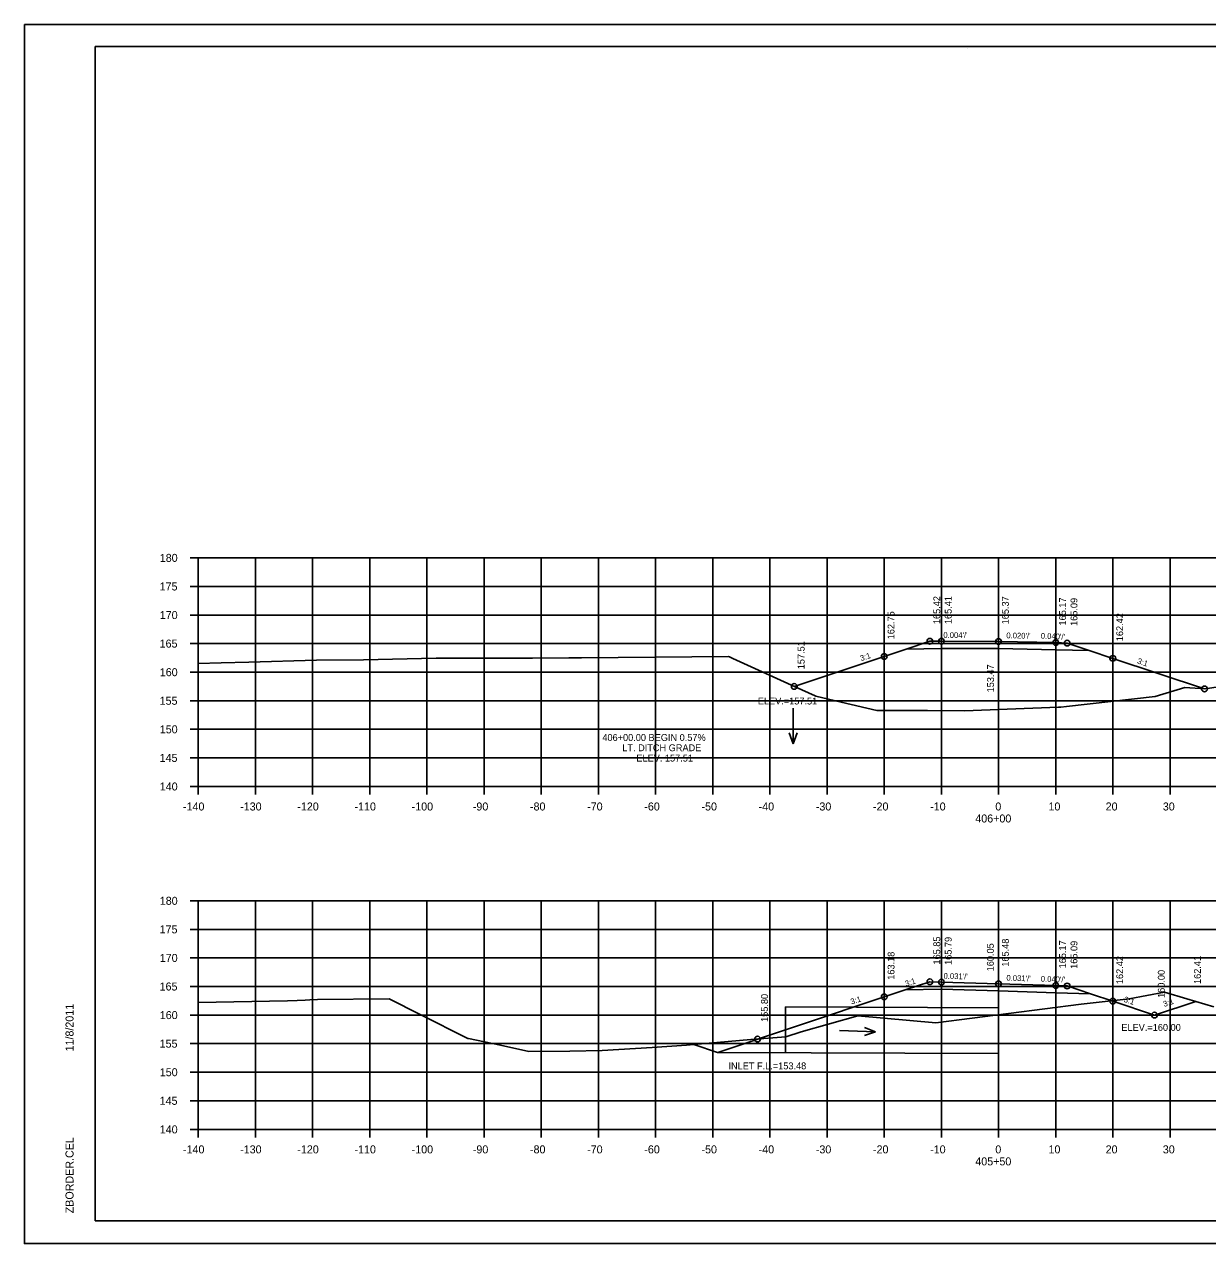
# Model space of a CAD drawing. Extents: x 1368503 to 1373085, y 379840 to 381833.
# Drawn here: x 1372751.7 to 1372958.7, y 380601.6 to 380815 of the extents above; entities that cross this region are included whole.
import ezdxf

# ---------------------------------------------------------------- set-up
doc = ezdxf.new("R2010")
doc.units = 0
for name, color, linetype in [('S_BREAKLINE', 7, 'Continuous'), ('S_BRIDGE', 7, 'Continuous'), ('S_EDGE_PAVEMENT', 7, 'Continuous'), ('S_GRAVEL_ROAD', 7, 'Continuous'), ('S_MISC_BOUNDARY', 7, 'Continuous'), ('S_OBSCURES', 7, 'Continuous'), ('S_PHOTO_CENTERS', 7, 'Continuous'), ('S_PHOTO_NOTES', 7, 'Continuous'), ('S_RDW_PT_SYM', 7, 'Continuous'), ('S_SHOULDER', 7, 'Continuous'), ('S_STREAM_ANNOT', 7, 'Continuous'), ('S_TRAILS', 7, 'Continuous'), ('S_TRAILS_ANNOT', 7, 'Continuous')]:
    doc.layers.add(name, color=color, linetype=linetype)

msp = doc.modelspace()

# ---------------------------------------------------------------- linework, layer by layer
at = {"layer": 'S_BREAKLINE'}
for p, q in [((1372884.84, 380643.05), (1372922.08, 380642.91)), ((1372884.84, 380635.05), (1372884.84, 380643.05)), ((1372872.94, 380635.09), (1372868.79, 380636.48)), ((1372872.94, 380635.09), (1372922.08, 380634.91))]:
    msp.add_line(p, q, dxfattribs=at)
at = {"layer": 'S_BRIDGE'}
for p, q in [((1372764.08, 380811.09), (1373080.26, 380811.09)), ((1372764.08, 380605.63), (1372764.08, 380811.09)), ((1372916.6, 380810.83), (1372916.6, 380810.83)), ((1372916.6, 380810.83), (1372916.6, 380810.83)), ((1372764.08, 380605.63), (1372764.08, 380605.63)), ((1373080.26, 380605.63), (1372764.08, 380605.63))]:
    msp.add_line(p, q, dxfattribs=at)
at = {"layer": 'S_EDGE_PAVEMENT'}
for p, q in [((1372780.68, 380721.63), (1372782.08, 380721.63)), ((1372782.08, 380681.63), (1372782.08, 380721.63)), ((1372780.68, 380716.63), (1372782.08, 380716.63)), ((1372780.68, 380711.63), (1372782.08, 380711.63)), ((1372780.68, 380706.63), (1372782.08, 380706.63)), ((1372780.68, 380701.63), (1372782.08, 380701.63)), ((1372780.68, 380696.63), (1372782.08, 380696.63)), ((1372780.68, 380691.63), (1372782.08, 380691.63)), ((1372780.68, 380686.63), (1372782.08, 380686.63)), ((1372780.68, 380681.63), (1372782.08, 380681.63)), ((1372782.08, 380681.63), (1373062.08, 380681.63)), ((1372782.08, 380680.23), (1372782.08, 380681.63)), ((1372792.08, 380680.23), (1372792.08, 380681.63)), ((1372802.08, 380680.23), (1372802.08, 380681.63)), ((1372812.08, 380680.23), (1372812.08, 380681.63)), ((1372822.08, 380680.23), (1372822.08, 380681.63)), ((1372832.08, 380680.23), (1372832.08, 380681.63)), ((1372842.08, 380680.23), (1372842.08, 380681.63)), ((1372852.08, 380680.23), (1372852.08, 380681.63)), ((1372862.08, 380680.23), (1372862.08, 380681.63)), ((1372872.08, 380680.23), (1372872.08, 380681.63)), ((1372882.08, 380680.23), (1372882.08, 380681.63)), ((1372892.08, 380680.23), (1372892.08, 380681.63)), ((1372902.08, 380680.23), (1372902.08, 380681.63)), ((1372912.08, 380680.23), (1372912.08, 380681.63)), ((1372922.08, 380680.23), (1372922.08, 380681.63)), ((1372932.08, 380680.23), (1372932.08, 380681.63)), ((1372942.08, 380680.23), (1372942.08, 380681.63)), ((1372952.08, 380680.23), (1372952.08, 380681.63)), ((1372780.68, 380661.63), (1372782.08, 380661.63)), ((1372782.08, 380621.63), (1372782.08, 380661.63)), ((1372780.68, 380656.63), (1372782.08, 380656.63)), ((1372780.68, 380651.63), (1372782.08, 380651.63)), ((1372780.68, 380646.63), (1372782.08, 380646.63)), ((1372780.68, 380641.63), (1372782.08, 380641.63)), ((1372780.68, 380636.63), (1372782.08, 380636.63)), ((1372780.68, 380631.63), (1372782.08, 380631.63)), ((1372780.68, 380626.63), (1372782.08, 380626.63)), ((1372780.68, 380621.63), (1372782.08, 380621.63)), ((1372782.08, 380621.63), (1373062.08, 380621.63)), ((1372782.08, 380620.23), (1372782.08, 380621.63)), ((1372792.08, 380620.23), (1372792.08, 380621.63)), ((1372802.08, 380620.23), (1372802.08, 380621.63)), ((1372812.08, 380620.23), (1372812.08, 380621.63)), ((1372822.08, 380620.23), (1372822.08, 380621.63)), ((1372832.08, 380620.23), (1372832.08, 380621.63)), ((1372842.08, 380620.23), (1372842.08, 380621.63)), ((1372852.08, 380620.23), (1372852.08, 380621.63)), ((1372862.08, 380620.23), (1372862.08, 380621.63)), ((1372872.08, 380620.23), (1372872.08, 380621.63)), ((1372882.08, 380620.23), (1372882.08, 380621.63)), ((1372892.08, 380620.23), (1372892.08, 380621.63)), ((1372902.08, 380620.23), (1372902.08, 380621.63)), ((1372912.08, 380620.23), (1372912.08, 380621.63)), ((1372922.08, 380620.23), (1372922.08, 380621.63)), ((1372932.08, 380620.23), (1372932.08, 380621.63)), ((1372942.08, 380620.23), (1372942.08, 380621.63)), ((1372952.08, 380620.23), (1372952.08, 380621.63))]:
    msp.add_line(p, q, dxfattribs=at)
at = {"layer": 'S_GRAVEL_ROAD'}
for p, q in [((1372886.17, 380695.36), (1372886.17, 380689.08)), ((1372886.17, 380689.08), (1372885.47, 380691)), ((1372886.17, 380689.08), (1372886.87, 380691)), ((1372900.55, 380638.7), (1372898.65, 380639.46)), ((1372894.27, 380638.91), (1372900.55, 380638.7)), ((1372900.55, 380638.7), (1372898.61, 380638.06))]:
    msp.add_line(p, q, dxfattribs=at)
at = {"layer": 'S_MISC_BOUNDARY'}
for points in [[(1372782.08, 380703.12), (1372786.08, 380703.24), (1372790.94, 380703.39), (1372802.76, 380703.74), (1372811, 380703.78), (1372823.72, 380704.09), (1372840.53, 380704.09), (1372846.89, 380704.12), (1372849.14, 380704.13), (1372874.87, 380704.37), (1372875.04, 380704.29), (1372875.62, 380704.03), (1372886.51, 380699.07), (1372890.03, 380697.47), (1372890.11, 380697.46), (1372890.12, 380697.45), (1372894.57, 380696.41), (1372900.78, 380694.94), (1372909.63, 380694.94), (1372916.11, 380694.86), (1372932.59, 380695.49), (1372932.98, 380695.51), (1372933.98, 380695.62), (1372949.5, 380697.4), (1372949.5, 380697.4), (1372949.51, 380697.4), (1372954.65, 380698.96), (1372958.21, 380698.7), (1372960.17, 380698.99)], [(1372782.08, 380643.85), (1372797.72, 380644.15), (1372799.4, 380644.21), (1372800.79, 380644.26), (1372801.6, 380644.29), (1372802.97, 380644.34), (1372815.49, 380644.49), (1372820.89, 380641.73), (1372829.26, 380637.53), (1372829.28, 380637.53), (1372829.39, 380637.52), (1372834.97, 380636.36), (1372839.91, 380635.27), (1372847.08, 380635.29), (1372852.76, 380635.41), (1372861.51, 380635.98), (1372867.52, 380636.37), (1372878.75, 380637.33), (1372884.87, 380637.81), (1372884.88, 380637.81), (1372884.89, 380637.82), (1372887.58, 380638.68), (1372897.49, 380641.47), (1372911.09, 380640.27), (1372936.53, 380643.54), (1372944.92, 380644.46), (1372951.14, 380645.64), (1372955.01, 380644.49), (1372959.73, 380643.1)]]:
    msp.add_lwpolyline(points, dxfattribs=at)
at = {"layer": 'S_OBSCURES'}
for points in [[(1372937.94, 380705.43), (1372932.08, 380705.55), (1372922.08, 380705.75), (1372912.08, 380705.79), (1372905.94, 380705.66)], [(1372938.15, 380645.36), (1372932.08, 380645.55), (1372922.08, 380645.85), (1372912.08, 380646.16), (1372905.77, 380646.04)]]:
    msp.add_lwpolyline(points, dxfattribs=at)
at = {"layer": 'S_PHOTO_CENTERS'}
for p, q in [((1372782.08, 380721.63), (1373062.08, 380721.63)), ((1372782.08, 380681.63), (1372782.08, 380721.63)), ((1372792.08, 380681.63), (1372792.08, 380721.63)), ((1372802.08, 380681.63), (1372802.08, 380721.63)), ((1372812.08, 380681.63), (1372812.08, 380721.63)), ((1372822.08, 380681.63), (1372822.08, 380721.63)), ((1372832.08, 380681.63), (1372832.08, 380721.63)), ((1372842.08, 380681.63), (1372842.08, 380721.63)), ((1372852.08, 380681.63), (1372852.08, 380721.63)), ((1372862.08, 380681.63), (1372862.08, 380721.63)), ((1372872.08, 380681.63), (1372872.08, 380721.63)), ((1372882.08, 380681.63), (1372882.08, 380721.63)), ((1372892.08, 380681.63), (1372892.08, 380721.63)), ((1372902.08, 380681.63), (1372902.08, 380721.63)), ((1372912.08, 380681.63), (1372912.08, 380721.63)), ((1372922.08, 380681.63), (1372922.08, 380721.63)), ((1372932.08, 380681.63), (1372932.08, 380721.63)), ((1372942.08, 380681.63), (1372942.08, 380721.63)), ((1372952.08, 380681.63), (1372952.08, 380721.63)), ((1372782.08, 380716.63), (1373062.08, 380716.63)), ((1372782.08, 380711.63), (1373062.08, 380711.63)), ((1372782.08, 380706.63), (1373062.08, 380706.63)), ((1372782.08, 380701.63), (1373062.08, 380701.63)), ((1372782.08, 380696.63), (1373062.08, 380696.63)), ((1372782.08, 380691.63), (1373062.08, 380691.63)), ((1372782.08, 380686.63), (1373062.08, 380686.63)), ((1372782.08, 380681.63), (1373062.08, 380681.63)), ((1372782.08, 380661.63), (1373062.08, 380661.63)), ((1372782.08, 380621.63), (1372782.08, 380661.63)), ((1372792.08, 380621.63), (1372792.08, 380661.63)), ((1372802.08, 380621.63), (1372802.08, 380661.63)), ((1372812.08, 380621.63), (1372812.08, 380661.63)), ((1372822.08, 380621.63), (1372822.08, 380661.63)), ((1372832.08, 380621.63), (1372832.08, 380661.63)), ((1372842.08, 380621.63), (1372842.08, 380661.63)), ((1372852.08, 380621.63), (1372852.08, 380661.63)), ((1372862.08, 380621.63), (1372862.08, 380661.63)), ((1372872.08, 380621.63), (1372872.08, 380661.63)), ((1372882.08, 380621.63), (1372882.08, 380661.63)), ((1372892.08, 380621.63), (1372892.08, 380661.63)), ((1372902.08, 380621.63), (1372902.08, 380661.63)), ((1372912.08, 380621.63), (1372912.08, 380661.63)), ((1372922.08, 380621.63), (1372922.08, 380661.63)), ((1372932.08, 380621.63), (1372932.08, 380661.63)), ((1372942.08, 380621.63), (1372942.08, 380661.63)), ((1372952.08, 380621.63), (1372952.08, 380661.63)), ((1372782.08, 380656.63), (1373062.08, 380656.63)), ((1372782.08, 380651.63), (1373062.08, 380651.63)), ((1372782.08, 380646.63), (1373062.08, 380646.63)), ((1372782.08, 380641.63), (1373062.08, 380641.63)), ((1372782.08, 380636.63), (1373062.08, 380636.63)), ((1372782.08, 380631.63), (1373062.08, 380631.63)), ((1372782.08, 380626.63), (1373062.08, 380626.63)), ((1372782.08, 380621.63), (1373062.08, 380621.63))]:
    msp.add_line(p, q, dxfattribs=at)
at = {"layer": 'S_PHOTO_NOTES'}
for p, q in [((1372751.68, 380814.98), (1373085.01, 380814.98)), ((1372751.68, 380601.65), (1373085.01, 380601.65))]:
    msp.add_line(p, q, dxfattribs=at)
for points in [[(1372751.67, 380814.98), (1373085.01, 380814.98), (1373085.01, 380601.64), (1372751.67, 380601.64)], [(1372998, 380811.09), (1372998, 380801.21), (1373033.73, 380801.21), (1373033.73, 380798.29), (1373056.93, 380798.29), (1373056.93, 380773.95), (1373080.26, 380773.95), (1373080.26, 380605.63), (1372764.08, 380605.63), (1372764.08, 380811.09)]]:
    msp.add_lwpolyline(points, close=True, dxfattribs=at)
for centre in [(1372910.08, 380707.04), (1372912.08, 380707.04), (1372922.08, 380707), (1372932.08, 380706.8), (1372934.08, 380706.72), (1372902.08, 380704.38), (1372942.08, 380704.05), (1372886.35, 380699.14), (1372958.11, 380698.7), (1372910.08, 380647.47), (1372912.08, 380647.41), (1372922.08, 380647.1), (1372932.08, 380646.8), (1372934.08, 380646.72), (1372902.08, 380644.81), (1372942.08, 380644.05), (1372949.35, 380641.63), (1372879.94, 380637.43)]:
    msp.add_circle(centre, 0.5, dxfattribs=at)
at = {"layer": 'S_STREAM_ANNOT'}
for points in [[(1372886.36, 380699.14), (1372902.08, 380704.38), (1372905.94, 380705.66), (1372910.08, 380707.04), (1372912.08, 380707.04), (1372922.08, 380707), (1372932.08, 380706.8), (1372934.08, 380706.72), (1372937.94, 380705.43), (1372942.08, 380704.05), (1372958.11, 380698.7)], [(1372872.97, 380635.11), (1372902.08, 380644.81), (1372905.77, 380646.04), (1372910.08, 380647.47), (1372912.08, 380647.41), (1372922.08, 380647.1), (1372932.08, 380646.8), (1372934.08, 380646.72), (1372938.15, 380645.36), (1372942.08, 380644.05), (1372949.35, 380641.63), (1372956.57, 380644.03)]]:
    msp.add_lwpolyline(points, dxfattribs=at)

# ---------------------------------------------------------------- texts
at = {"layer": 'S_BRIDGE'}
for s, p in [('11/8/2011', (1372760.27, 380635.27)), ('ZBORDER.CEL', (1372760.27, 380606.95))]:
    msp.add_text(s, height=1.4, rotation=90, dxfattribs=at).set_placement(p)
at = {"layer": 'S_GRAVEL_ROAD'}
for s, p in [('ELEV.=157.51', (1372879.97, 380695.98)), ('406+00.00 BEGIN 0.57%', (1372852.78, 380689.6)), ('LT. DITCH GRADE', (1372856.27, 380687.8)), ('ELEV. 157.51', (1372858.73, 380686)), ('ELEV.=160.00', (1372943.57, 380638.87)), ('INLET F.L.=153.48', (1372874.84, 380632.14))]:
    msp.add_text(s, height=1.2, dxfattribs=at).set_placement(p)
at = {"layer": 'S_RDW_PT_SYM'}
for s, rotation, p in [("0.004'/'", 359.7671, (1372912.43, 380707.63)), ("0.020'/'", 358.8542, (1372923.44, 380707.57)), ("0.040'/'", 357.7094, (1372929.46, 380707.5)), ('3:1', 18.4338, (1372898.06, 380703.56)), ('3:1', 341.5662, (1372946.26, 380703.18)), ('3:1', 18.4349, (1372905.92, 380646.61)), ("0.031'/'", 358.234, (1372912.45, 380648)), ("0.031'/'", 358.234, (1372923.45, 380647.66)), ("0.040'/'", 357.7094, (1372929.46, 380647.5)), ('3:1', 18.4337, (1372896.38, 380643.46)), ('3:1', 341.5662, (1372943.91, 380643.97)), ('3:1', 18.4338, (1372951.07, 380643.04))]:
    msp.add_text(s, height=1, rotation=rotation, dxfattribs=at).set_placement(p)
at = {"layer": 'S_SHOULDER'}
for s, p in [('165.42', (1372911.88, 380710.04)), ('165.41', (1372913.88, 380710.04)), ('165.37', (1372923.88, 380710)), ('165.17', (1372933.88, 380709.8)), ('165.09', (1372935.88, 380709.72)), ('162.75', (1372903.88, 380707.38)), ('162.42', (1372943.88, 380707.05)), ('157.51', (1372888.15, 380702.14)), ('165.85', (1372911.88, 380650.47)), ('165.79', (1372913.88, 380650.41)), ('165.48', (1372923.88, 380650.1)), ('165.17', (1372933.88, 380649.8)), ('165.09', (1372935.88, 380649.72)), ('163.18', (1372903.88, 380647.81)), ('162.41', (1372957.48, 380647.07)), ('162.42', (1372943.88, 380647.05)), ('160.00', (1372951.15, 380644.63)), ('155.80', (1372881.74, 380640.43))]:
    msp.add_text(s, height=1.2, rotation=90, dxfattribs=at).set_placement(p)
at = {"layer": 'S_TRAILS'}
for s, p in [('180', (1372775.36, 380720.93)), ('175', (1372775.33, 380715.93)), ('170', (1372775.36, 380710.93)), ('165', (1372775.33, 380705.93)), ('160', (1372775.36, 380700.93)), ('155', (1372775.33, 380695.93)), ('150', (1372775.36, 380690.93)), ('145', (1372775.33, 380685.93)), ('140', (1372775.36, 380680.93)), ('-140', (1372779.42, 380677.43)), ('-130', (1372789.42, 380677.43)), ('-120', (1372799.42, 380677.43)), ('-110', (1372809.42, 380677.43)), ('-100', (1372819.42, 380677.43)), ('-90', (1372830.12, 380677.43)), ('-80', (1372840.12, 380677.43)), ('-70', (1372850.12, 380677.43)), ('-60', (1372860.12, 380677.43)), ('-50', (1372870.12, 380677.43)), ('-40', (1372880.12, 380677.43)), ('-30', (1372890.12, 380677.43)), ('-20', (1372900.12, 380677.43)), ('-10', (1372910.12, 380677.43)), ('0', (1372921.52, 380677.43)), ('10', (1372930.82, 380677.43)), ('20', (1372940.82, 380677.43)), ('30', (1372950.82, 380677.43)), ('406+00', (1372918.02, 380675.33)), ('180', (1372775.36, 380660.93)), ('175', (1372775.33, 380655.93)), ('170', (1372775.36, 380650.93)), ('165', (1372775.33, 380645.93)), ('160', (1372775.36, 380640.93)), ('155', (1372775.33, 380635.93)), ('150', (1372775.36, 380630.93)), ('145', (1372775.33, 380625.93)), ('140', (1372775.36, 380620.93)), ('-140', (1372779.42, 380617.43)), ('-130', (1372789.42, 380617.43)), ('-120', (1372799.42, 380617.43)), ('-110', (1372809.42, 380617.43)), ('-100', (1372819.42, 380617.43)), ('-90', (1372830.12, 380617.43)), ('-80', (1372840.12, 380617.43)), ('-70', (1372850.12, 380617.43)), ('-60', (1372860.12, 380617.43)), ('-50', (1372870.12, 380617.43)), ('-40', (1372880.12, 380617.43)), ('-30', (1372890.12, 380617.43)), ('-20', (1372900.12, 380617.43)), ('-10', (1372910.12, 380617.43)), ('0', (1372921.52, 380617.43)), ('10', (1372930.82, 380617.43)), ('20', (1372940.82, 380617.43)), ('30', (1372950.82, 380617.43)), ('405+50', (1372918.02, 380615.33))]:
    msp.add_text(s, height=1.4, dxfattribs=at).set_placement(p)
at = {"layer": 'S_TRAILS_ANNOT'}
for s, p in [('153.47', (1372921.28, 380698.09)), ('160.05', (1372921.25, 380649.29))]:
    msp.add_text(s, height=1.2, rotation=90, dxfattribs=at).set_placement(p)

doc.saveas('drawing.dxf')
